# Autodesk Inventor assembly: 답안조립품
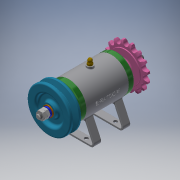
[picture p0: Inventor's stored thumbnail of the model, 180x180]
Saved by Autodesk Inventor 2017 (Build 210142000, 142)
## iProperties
Part Number: 답안조립품
Material: 일반
Document SubType Name: Assembly
Designer: Administrator
Author: Administrator
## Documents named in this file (16)
- C:\Users\Administrator\Desktop\711206V1026\답안조립품.iam
- C:\Users\Administrator\Desktop\711206V1026\본체.ipt
- C:\Users\Administrator\Desktop\711206V1026\축.ipt
- C:\Users\Administrator\Desktop\711206V1026\키 3 x 3.ipt
- C:\Users\Administrator\Desktop\711206V1026\베어링 6002.ipt
- C:\Users\Administrator\Desktop\711206V1026\커버.ipt
- C:\Users\Administrator\Desktop\711206V1026\오일 실 15 x 25 x 7.ipt
- C:\Users\Administrator\Desktop\711206V1026\볼트 M4 x 12.ipt
- C:\Users\Administrator\Desktop\711206V1026\V벨트풀리.ipt
- C:\Users\Administrator\Desktop\711206V1026\와셔 8 x 17.ipt
- C:\Users\Administrator\Desktop\711206V1026\너트 M8.ipt
- C:\Users\Administrator\Desktop\711206V1026\스프링와셔 8.ipt
- C:\Users\Administrator\Desktop\711206V1026\스프로킷.ipt
- C:\Users\Administrator\Desktop\711206V1026\니플 M6 x 0.75.ipt
- C:\Users\Administrator\Desktop\711206V1026\볼트 M6 x 8.ipt
- C:\Users\Administrator\Desktop\711206V1026\와셔 6 x 11.5.ipt
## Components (11 placed, 3 different names)
1. KS B 2023 6002 - 15 x 32 x 9:1
2. KS B 2023 6002 - 15 x 32 x 9:2
3. V벨트풀리:1
4. ISO 4762 M4 x 12:1
5. ISO 4762 M4 x 12:2
6. ISO 4762 M4 x 12:3
7. ISO 4762 M4 x 12:4
8. ISO 4762 M4 x 12:5
9. ISO 4762 M4 x 12:6
10. ISO 4762 M4 x 12:7
11. ISO 4762 M4 x 12:8
